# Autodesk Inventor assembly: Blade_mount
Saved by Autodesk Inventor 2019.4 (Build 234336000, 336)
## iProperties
Created: 2020-02
Part Number: Blade_mount
Document SubType Name: Assembly
Designer: Administrator
Title: Blade_mount v18
Author: Administrator
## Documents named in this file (10)
- c:\worker\convert-fusion-r01\tmp\job-1\5\output\files\e4333473-a38b-4431-9958-ad24a2f67704\Blade_mount v18_1.iam
- c:\worker\convert-fusion-r01\tmp\job-1\5\output\files\e4333473-a38b-4431-9958-ad24a2f67704\Component1.ipt
- c:\worker\convert-fusion-r01\tmp\job-1\5\output\files\e4333473-a38b-4431-9958-ad24a2f67704\Component2.ipt
- c:\worker\convert-fusion-r01\tmp\job-1\5\output\files\e4333473-a38b-4431-9958-ad24a2f67704\Component3.ipt
- c:\worker\convert-fusion-r01\tmp\job-1\5\output\files\e4333473-a38b-4431-9958-ad24a2f67704\Component4.ipt
- c:\worker\convert-fusion-r01\tmp\job-1\5\output\files\e4333473-a38b-4431-9958-ad24a2f67704\Component5.ipt
- c:\worker\convert-fusion-r01\tmp\job-1\5\output\files\e4333473-a38b-4431-9958-ad24a2f67704\Component6.ipt
- c:\worker\convert-fusion-r01\tmp\job-1\5\output\files\e4333473-a38b-4431-9958-ad24a2f67704\Component7.ipt
- c:\worker\convert-fusion-r01\tmp\job-1\5\output\files\e4333473-a38b-4431-9958-ad24a2f67704\Component8.ipt
- c:\worker\convert-fusion-r01\tmp\job-1\5\output\files\e4333473-a38b-4431-9958-ad24a2f67704\Component9.ipt
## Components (9 placed, 9 different names)
1. Component1:1
2. Component2:1
3. Component3:1
4. Component4:1
5. Component5:1
6. Component6:1
7. Component7:1
8. Component8:1
9. Component9:1
